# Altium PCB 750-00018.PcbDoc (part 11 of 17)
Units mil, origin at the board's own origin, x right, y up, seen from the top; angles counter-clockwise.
Board outline 7086.64 x 6299.21 mil, 8 copper layers (Top Layer, L2, L3, L4, L5, L6, L7, Bottom Layer), stack 60.6 mil thick; 1356 components, 1054 nets, 4851 pads, 4296 vias.
Unrouted connection lines stored in the file: 12.
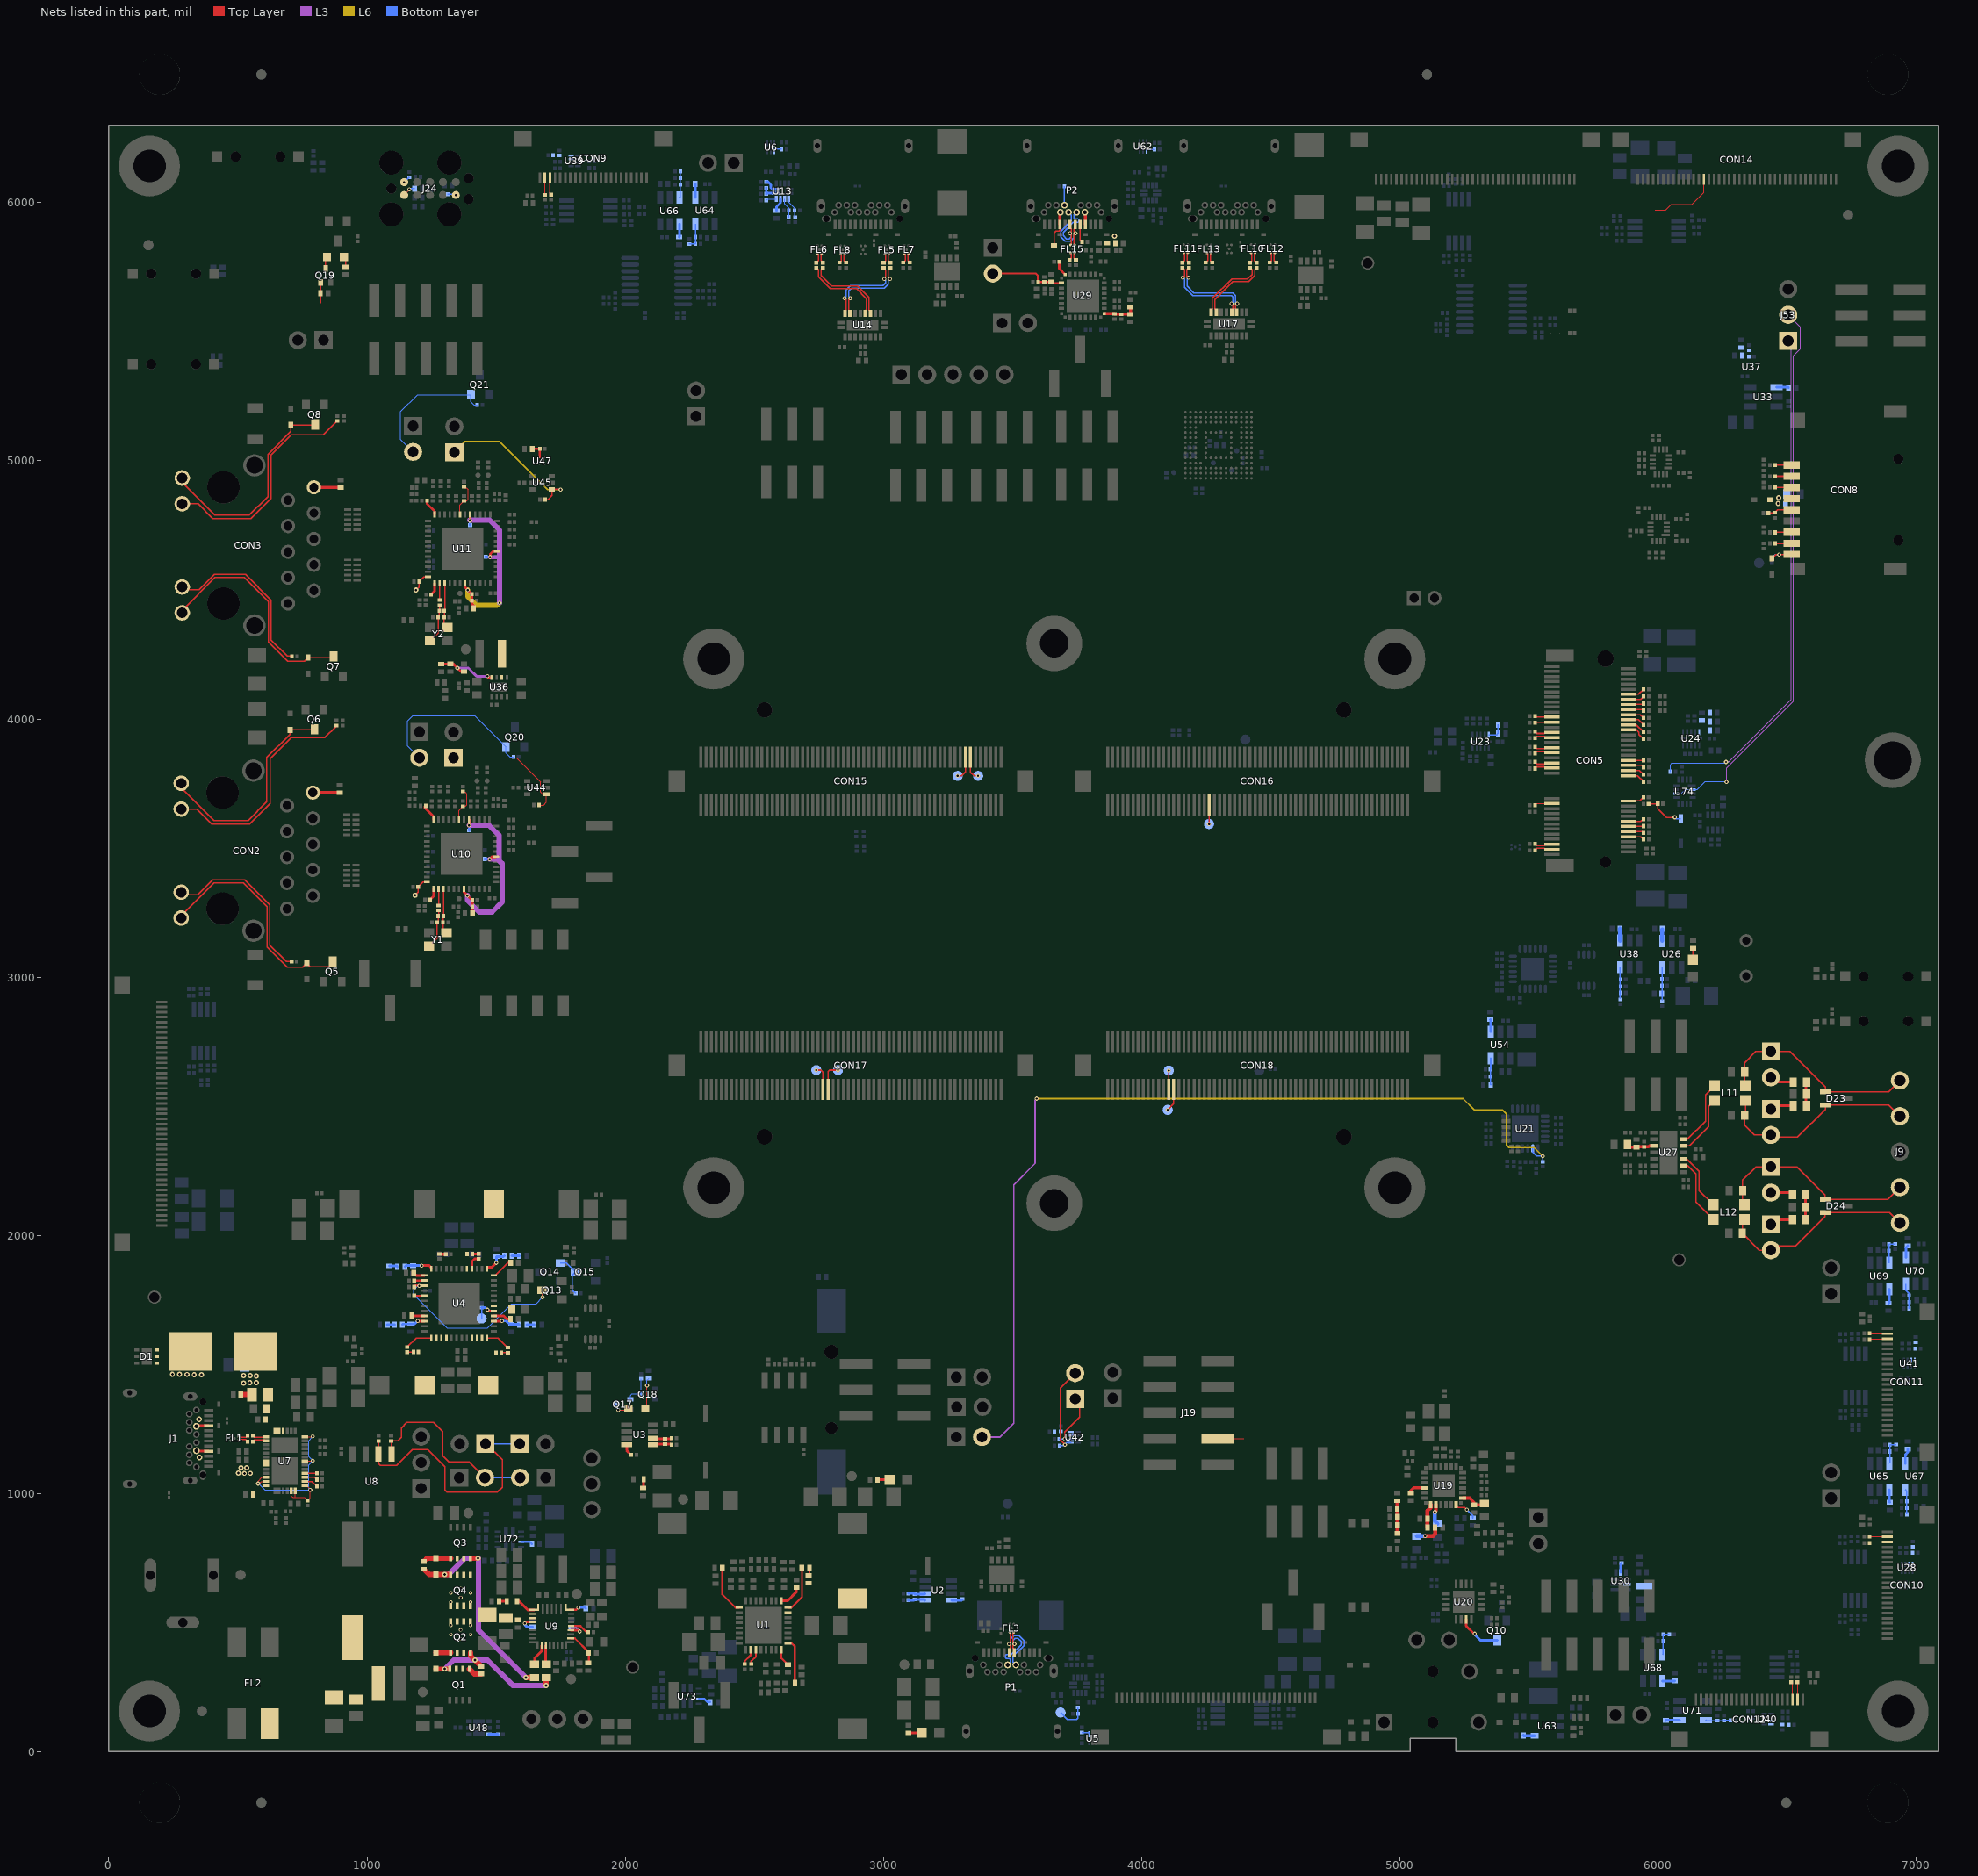
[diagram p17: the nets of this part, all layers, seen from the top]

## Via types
v1: diameter 16, hole 8, Top Layer to Bottom Layer, tented both sides, 3994 vias
v2: diameter 20, hole 10, Top Layer to Bottom Layer, tented both sides, 266 vias
v3: diameter 14, hole 7.87, Top Layer to Bottom Layer, tented both sides, 24 vias
v4: diameter 22, hole 12, Top Layer to Bottom Layer, tented both sides, 8 vias
v5: diameter 24, hole 12, Top Layer to Bottom Layer, tented both sides, 4 vias

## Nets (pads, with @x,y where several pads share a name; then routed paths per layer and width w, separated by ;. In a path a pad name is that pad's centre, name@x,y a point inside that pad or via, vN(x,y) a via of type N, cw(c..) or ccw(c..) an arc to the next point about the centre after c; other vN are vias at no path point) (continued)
NetC20_1: C20.1 R12.2 | length 32
  Top Layer w8: C20.1@2709.93,682.36 2713.4,685.83 R12.2@2713.4,712.9
NetC20_2: C20.2 L3.1 U1.15
NetC21_2: C21.2 U1.8 | length 67.9
  Top Layer w8: U1.8@2604.21,395.25 2604.21,362.79 C21.2@2629.25,337.75
NetC25_2: C25.2 U1.17 | length 90.1
  Top Layer w10: U1.17@2604.21,584.25 2627.99,584.25 2663.13,619.39 C25.2@2663.13,635.98
NetC28_1: C28.1 R25.2 U2.2 | length 66.9
  Bottom Layer w10: R25.2@3096.59,613.02 3118.41,613.02 C28.1@3121.49,609.94 3158.47,609.94 U2.2@3161.1,612.57
NetC28_2: C28.2 R19.2 U2.1 | length 67.4
  Bottom Layer w10: R19.2@3096.41,586.99 3118.23,586.99 C28.2@3121.49,590.25 3157.83,590.25 U2.1@3161.1,586.98
NetC29_1: C29.1 R29.2 U3.2 | length 72.2
  Top Layer w10: U3.2@2107.75,1214.56 2109.94,1212.37 C29.1@2153.58,1212.37 ; C29.1@2154.12,1211.84 2177.32,1211.84 R29.2@2178.94,1213.46
NetC29_2: C29.2 R24.2 U3.1 | length 73
  Top Layer w10: U3.1@2107.75,1188.97 2110.32,1191.54 C29.2@2153.5,1191.54 ; C29.2@2154.52,1191.75 2174.59,1191.75 R24.2@2178.94,1187.4
NetC32_1: C32.1 R27.2 | length 25.1
  Top Layer w5: R27.2@1154.82,1547.92 1178.59,1547.92 C32.1@1179.51,1548.85
NetC32_2: C32.2 L4.1 U4.2 U4.3 U4.4
NetC33_1: C33.1 U4.45 | length 46.9
  Top Layer w10: C33.1@1175.9,1687.67 U4.45@1222.82,1687.67
NetC37_1: C37.1 U4.16 | length 70.3
  Top Layer w10: U4.16@1490.54,1687.67 1529.48,1687.67 1541.45,1675.7 C37.1@1555.87,1675.7
NetC38_1: C38.1 U4.24 | length 86
  Top Layer w5: U4.24@1490.54,1845.15 1497.07,1845.15 1546.41,1894.5 C38.1@1556.1,1894.5
NetC42_1: C42.1 R31.2 | length 25.7
  Top Layer w5: C42.1@1519.85,1546.47 1520.41,1545.91 R31.2@1545.32,1545.91
NetC42_2: C42.2 L5.1 U4.9 U4.10 U4.11
NetC49_1: C49.1 R37.2 | length 24.6
  Top Layer w10: C49.1@1407.55,1927.83 1431.01,1927.83 R37.2@1431.8,1928.63
NetC49_2: C49.2 L6.1 U4.29
NetC56_2: C56.2 R39.1 | length 28.7
  Bottom Layer w10: C56.2@1078.52,1653.96 1078.72,1654.16 R39.1@1107.19,1654.16
NetC57_1: C57.1 U4.18 | length 2.9
  Top Layer w10: C57.1@1558.32,1712.31 C57.1@1560.36,1714.36
NetC59_1: C59.1 R39.2 U4.46 | length 92
  Top Layer w10: v1@1195.86,1668.64 1196.51,1667.99 U4.46@1222.82,1667.99
  Bottom Layer w10: R39.2@1136.71,1654.16 1139.08,1656.52 C59.1@1167.67,1656.52 1183.74,1656.52 v1(1195.58,1668.36)
NetC60_1: C60.1 R41.2 U4.25 | length 104.3
  Top Layer w10: U4.25@1464.95,1870.74 1464.95,1876.36 1483.32,1876.36 v1(1500.6,1893.64)
  Bottom Layer w10: v1(1500.6,1893.64) 1501.15,1894.19 C60.1@1501.15,1917.24 1528.66,1917.24 R41.2@1531.86,1920.44
NetC61_2: C61.2 R41.1 | length 28.5
  Bottom Layer w10: R41.1@1561.39,1920.44 1589.02,1920.44 C61.2@1589.65,1921.06
NetC62_1: C62.1 R42.2 U4.15 | length 105.3
  Top Layer w10: U4.15@1490.54,1667.99 1521.84,1667.99 v1(1522.38,1668.52)
  Bottom Layer w10: v1(1522.38,1668.52) 1539.36,1668.52 1552.54,1655.34 C62.1@1558.25,1655.34 1587.42,1655.34 R42.2@1589.36,1653.4
NetC64_2: C64.2 R42.1 | length 28.6
  Bottom Layer w10: R42.1@1618.89,1653.4 1647.26,1653.4 C64.2@1647.41,1653.55
NetC66_1: C66.1 R43.2 | length 24.9
  Top Layer w12: R43.2@1280.96,1927.5 C66.1@1304.92,1927.5 ; R43.2@1281.68,1927.72 R43.2@1282.32,1927.08
NetC75_2: C75.2 U7.38
NetC76_2: C76.2 C77.2 C78.2 C79.2 F1.2 U7.23 U7.24 U7.25 U7.32 U7.33
  other v2: 524.66,1078.48 548.13,1078.61 501.8,1079.92 511.38,1100 534.17,1099.82 521.66,1428.44 546.44,1429.21 571.82,1430.2 571.82,1454.65 521.42,1456.22 546.87,1456.67
NetC77_1: C77.1 R54.2 | length 37.3
  Top Layer w20: R54.2@515.75,1383.62 C77.1@553.07,1383.62
NetC88_1: C88.1 D4.2 Q1.1 Q1.2 Q1.3 Q2.1 Q2.2 Q2.3 | length 111.3
  Top Layer w20: D4.2@1266.35,384.42 1267.21,383.57 Q2.1@1323.78,383.57 ; Q1.1@1396.11,320.5 1415.3,301.31 C88.1@1441.74,301.31
NetC88_2: C88.2 D4.1 Q1.4 Q2.4 R65.1 | length 592.5
  Top Layer w20: D4.1@1266.35,321.43 1267.28,320.5 v2(1300.46,320.5) Q1.4@1314.74,320.5 ; Q2.4@1400.55,383.57 1400.55,372.2 v2(1417.4,355.36) 1417.4,355.18 C88.2@1438.7,333.87 ; v2(1693.36,257.02) 1693.8,257.46 R65.1@1693.8,287
  L3 w20: v2(1300.46,320.5) 1335.32,355.36 v2(1417.4,355.36) 1466.35,355.36 1564.68,257.02 v2(1693.36,257.02)
NetC89_1: C89.1 C94.1 C95.1 Q2.5 Q2.6 Q2.7 Q2.8 Q4.5 Q4.6 Q4.7 Q4.8 U9.2 U9.3
  other v3: 1362.17,436.44 1323.78,454.24 1400.55,454.24 1362.17,472.07 1323.78,489.87 1400.55,489.87 1324.05,579.42 1400.82,579.42 1362.43,597.22 1324.05,615.05 1400.82,615.05 1362.43,632.85
NetC92_1: C92.1 D5.2 Q3.1 Q3.2 Q3.3 Q4.1 Q4.2 Q4.3 | length 106.2
  Top Layer w20: C92.1@1222.45,739.48 1233.08,750.11 D5.2@1266.35,750.11 1267.67,748.79 Q3.1@1323.74,748.79
NetC92_2: C92.2 D5.1 Q3.4 Q4.4 R66.1 | length 852.9
  Top Layer w20: C92.2@1223.13,704.06 1240.07,687.12 D5.1@1266.35,687.12 v2(1300.42,687.12) Q4.4@1318.94,687.12 ; Q3.4@1406.18,748.79 1429.46,748.79 v2(1429.63,748.96) ; v2(1615.67,287.2) 1615.77,287.09 R66.1@1648.69,287.09
  L3 w20: v2@1301.05,687.28 1317.16,687.28 1345.93,716.05 1379.72,749.85 v2@1429.63,749.85 ; v2@1431.42,749.85 1431.42,471.45 v2(1615.67,287.2)
NetC96_1: C96.1 U9.4 | length 69.7
  Top Layer w10: v1(1611.12,496.74) 1616.68,502.31 U9.4@1640.77,502.31
  Bottom Layer w10: v1(1611.12,496.74) 1611.12,492.16 1619.67,483.6 C96.1@1640.77,483.6
NetC97_1: C97.1 U9.19 | length 76.1
  Top Layer w10: U9.19@1789.39,470.81 1818.78,470.81 1823.01,466.58 v1(1823.01,465.51)
  Bottom Layer w10: C97.1@1791.09,482.7 1806.89,482.7 1823.01,466.58 v1(1823.01,465.51)
NetC109_1: C109.1 U9.24 | length 68.4
  Top Layer w8: U9.24@1783.49,549.55 1809.39,549.55 v1(1818.16,558.33)
  Bottom Layer w8: v1(1818.16,558.33) 1844.24,558.33 C109.1@1847.1,555.47
NetC110_1: C110.1 C111.1 C115.1 FL2.4 L9.1
NetC119_2: C119.2 C120.1 C121.1 C122.1 FB1.2 U10.19 U10.30 U10.41 | length 813.8
  Top Layer w10: U10.19@1375.38,3342.81 1375.38,3329.15 v1@1388.45,3316.08 ; v1(1388.57,3316.2) 1406.85,3297.92 C120.1@1407.59,3297.92 1407.76,3297.76 C119.2@1407.76,3272.58 ; v1(1395.07,3588.07) U10.41@1395.07,3610.53 ; FB1.2@1408.34,3246.58 C119.2@1408.34,3268.25 ; v1(1474.49,3457.27) 1484.05,3466.83 U10.30@1499.4,3466.83
  L3 w20: v1(1388.57,3316.2) 1388.57,3297.68 1434.04,3252.21 1484.17,3252.21 1522.64,3290.68 1522.64,3440.37 1505.94,3457.07 ; v1(1395.07,3588.07) 1472.44,3588.07 1510.78,3549.74 1510.78,3461.9 1505.94,3457.07 ; v1@1474.7,3457.07 1505.94,3457.07
  Bottom Layer w10: v1(1395.07,3588.07) 1395.32,3587.82 C122.1@1395.32,3568.31 ; C121.1@1456.09,3457.7 1474.06,3457.7 v1(1474.49,3457.27)
NetC138_2: C138.2 CON2.1 | length 103.9
  Top Layer w12: CON2.1@790,3715 892.87,3715 C138.2@893.57,3714.3
NetC139_1: C139.1 R87.1 U10.43 | length 136
  Top Layer w4: U10.43@1355.7,3610.53 1355.7,3646.43 C139.1@1371.42,3662.15 1381.08,3662.15 1386.8,3667.87 1386.8,3709.27 1379.43,3716.64 R87.1@1371.13,3716.64
NetC142_1: C142.1 R91.2 R92.1 Y1.1 | length 152.6
  Top Layer w5: Y1.1@1240.44,3120.98 1270.94,3151.48 C142.1@1270.94,3212.5 1275.65,3217.22 R92.1@1275.65,3236.84 1276.99,3238.17 R91.2@1276.99,3258.45
NetC143_2: C143.2 R92.2 U10.15 Y1.3 | length 177
  Top Layer w5: U10.15@1296.64,3342.81 1296.64,3238.14 R92.2@1295.34,3236.84 1295.34,3213.44 C143.2@1294.28,3212.39 1294.28,3185.25 Y1.3@1307.37,3172.17
NetC145_2: C145.2 C146.1 C147.1 C148.1 FB3.2 U11.19 U11.30 U11.41 | length 829.9
  Top Layer w10: U11.19@1379.32,4525.13 1379.32,4509.99 v1(1389.71,4499.6) 1405.39,4483.93 C148.1@1405.9,4483.93 1405.9,4458.21 C146.1@1405.69,4458 1405.69,4446.45 1412.28,4439.86 FB3.2@1412.28,4428.89 ; v1(1398.86,4768.87) 1399.01,4769.01 U11.41@1399.01,4792.84 ; v1(1476.78,4627.17) 1477.21,4627.6 1477.21,4639.06 1487.3,4649.14 U11.30@1503.34,4649.14
  L3 w15: v1(1476.78,4627.17) 1512.75,4627.17 1513.29,4627.71
  L3 w20: v1@1397.59,4770.06 1474.96,4770.06 1513.29,4731.72 1513.29,4627.71 v1(1513.29,4450.2)
  L6 w20: v1(1389.71,4499.6) 1389.71,4474.29 1423.68,4440.32 1503.41,4440.32 v1(1513.29,4450.2)
  Bottom Layer w10: v1(1398.86,4768.87) 1399.27,4768.46 C145.2@1399.27,4750.64 ; C147.1@1459.44,4627.97 1459.6,4628.13 1475.82,4628.13 v1(1476.78,4627.17)
NetC164_2: C164.2 CON3.1 | length 103.9
  Top Layer w12: CON3.1@793.94,4897.31 896.81,4897.31 C164.2@897.51,4896.61
NetC165_1: C165.1 R120.1 U11.43 | length 132.9
  Top Layer w4: U11.43@1359.64,4792.84 1359.64,4828.74 C165.1@1375.36,4844.47 1385.03,4844.47 1390.74,4850.18 1390.74,4889.07 1384.72,4895.09 R120.1@1375.07,4895.09
NetC168_1: C168.1 R124.2 R125.1 Y2.1 | length 152.6
  Top Layer w5: Y2.1@1244.38,4303.3 1275.25,4334.16 C168.1@1275.25,4394.48 1279.6,4398.83 R125.1@1279.6,4419.16 1280.93,4420.49 R124.2@1280.93,4440.76
NetC169_2: C169.2 R125.2 U11.15 Y2.3 | length 177
  Top Layer w5: U11.15@1300.58,4525.13 1300.58,4420.46 R125.2@1299.28,4419.16 1299.28,4395.76 C169.2@1298.23,4394.7 1298.23,4367.57 Y2.3@1311.31,4354.48
NetC194_1: C194.1 U19.24 | length 92
  Top Layer w6: U19.24@5217.9,956.94 5217.9,954.28 5225.96,946.22 5250.92,946.22 v1(5259.28,937.86)
  Bottom Layer w6: v1(5259.28,937.86) 5281.67,915.48 C194.1@5281.67,905.94
NetC195_2: C195.2 C196.1 U19.1 | length 102.8
  Top Layer w12: U19.1@5243.49,982.53 5270.88,982.53 5286.87,966.53 C196.1@5286.87,956.12 5323.46,956.12 C195.2@5327.53,960.19
NetC202_1: C202.1 U19.20 | length 78.7
  Top Layer w15: v1(5135.53,928.2) 5139.16,931.82 U19.20@5139.16,956.94
  Bottom Layer w15: v1(5135.53,928.2) 5135.53,892.76 C202.1@5144.76,883.54
NetC203_1: C203.1 R274.1 R276.1 | length 98.8
  Top Layer w15: v1(5097.49,835.46) 5127.96,835.46 5136.3,843.8 R276.1@5136.3,867.94
  Bottom Layer w15: C203.1@5065.31,834.86 5096.89,834.86 v1(5097.49,835.46)
NetC209_1: C209.1 C212.2 FB8.1 R204.1 R205.1 | length 127.9
  Top Layer w15: C212.2@4990.14,972.69 4990.14,942.66 R205.1@4989.7,942.22 4990.61,941.31 C209.1@4990.61,909.31 R204.1@4990.61,876.54 ; R204.1@4990.44,876.37 R204.1@4990.61,876.54 ; FB8.1@4990.5,845.69 4990.61,845.8 R204.1@4990.61,876.54
NetC222_1: C222.1 C254.1 FB9.1 U27.3 | length 108
  Top Layer w12: FB9.1@5881.17,2351.44 5890.62,2341.99 C254.1@5916.39,2341.99 5917.35,2342.95 C222.1@5946.16,2342.95 5962.55,2342.95 5966.16,2346.56 U27.3@5983.31,2346.56
NetC231_1: C231.1 R224.1 U23.11 | length 72.3
  Bottom Layer w5: U23.11@5344.43,3938.54 5374.3,3938.54 C231.1@5380.32,3944.56 5380.32,3978.18 R224.1@5380.55,3978.41
NetC233_1: C233.1 R222.1 R223.1 R225.1 U24.11
NetC246_1: C246.1 U26.4 | length 47.5
  Bottom Layer w10: C246.1@6015.61,3184.48 C246.1@6018.11,3186.98
  Bottom Layer w15: U26.4@6015.61,3140.5 C246.1@6015.61,3184.48
NetC247_1: C247.1 R26.1 R244.2 R248.2 U26.3 | length 126.8
  Bottom Layer w6: R26.1@6015.61,2911.34 6015.61,2966.47 U26.3@6015.61,3038.14
NetC248_1: C248.1 CON5.37 | length 70.5
  Top Layer w6: C248.1@5523,3833.36 5530.24,3826.13 5559.52,3826.13 5563.24,3829.84 CON5.37@5588.98,3829.84
NetC249_1: C249.1 CON5.35 | length 71.2
  Top Layer w6: C249.1@5522.92,3807.69 5530.36,3815.13 5559.17,3815.13 5564.14,3810.16 CON5.35@5588.98,3810.16
NetC256_2: C256.2 R285.1 U28.7 U28.8
NetC257_2: C257.2 R353.1 U39.7 U39.8
NetC258_2: C258.2 R377.1 U40.7 U40.8
NetC259_2: C259.2 R378.1 U41.7 U41.8
NetC260_2: C260.2 R519.1 U42.7 U42.8
NetC262_1: C262.1 R526.2 R530.2 R538.2 U37.5
NetC264_1: C264.1 R275.1 R277.2 | length 91.3
  Top Layer w10: R277.2@6572.49,2494.15 R275.1@6572.49,2585.41
NetC265_1: C265.1 D23.1 J7.1 J9.5 L11.3 | length 803.6
  Top Layer w5: L11.3@6338.8,2579.56 6334.96,2583.4 C265.1@6334.96,2633.34 6334.96,2668.51 6378.33,2711.88 J7.1@6436.53,2711.88 6509.91,2711.88 6647.18,2574.61 D23.1@6647.18,2555.88 6892.49,2555.88 J9.5@6936.31,2599.7
NetC266_1: C266.1 D23.2 J8.2 J9.4 L11.2 | length 797.6
  Top Layer w5: C266.1@6332.97,2466.38 6338.8,2472.22 L11.2@6338.8,2522.47 ; C266.1@6334.96,2466.38 6334.96,2426.28 6372.38,2388.86 J8.2@6436.53,2388.86 6444.57,2380.81 6539.88,2380.81 6647.18,2488.11 D23.2@6647.18,2504.7 6893.51,2504.7 J9.4@6936.31,2461.9
NetC269_1: C269.1 R537.2 U47.5 | length 61.3
  Top Layer w9: R537.2@1639.63,5045.69 1640.14,5046.21 C269.1@1668.96,5046.21 1668.85,5046.09 U47.5@1668.85,5014.54
NetC270_2: C270.2 U48.3 | length 35
  Bottom Layer w12: U48.3@1471.37,66.79 1505.66,66.79 C270.2@1506.14,67.28
NetC273_1: C273.1 D25.1 FB13.2 P2.A4 P2.A9 P2.B4 P2.B9 | length 194
  Top Layer w5: D25.1@3660.93,5833.49 3660.93,5882.14 3668.15,5889.35 3679,5889.35 3683.3,5893.65 P2.A9@3683.3,5914.96
  Top Layer w12: P2.A9@3683.3,5914.96 3683.3,5960.64 P2.B4@3685.26,5962.6 ; P2.B9@3779.75,5962.6 3781.72,5960.63 P2.A4@3781.72,5914.96
  other v2: 3895.4,5869.81
NetC276_1: C276.1 U19.16 | length 64.7
  Top Layer w12: C276.1@5041.72,1002.44 5041.72,1010.03 5053.58,1021.9 U19.16@5093.89,1021.9
NetC277_1: C277.1 R282.1 R284.2 | length 91.3
  Top Layer w10: R284.2@6570.26,2052.23 R282.1@6570.26,2143.49
NetC278_1: C278.1 D24.1 J9.2 J10.1 L12.3 | length 809.9
  Top Layer w5: L12.3@6333.91,2118.96 6327.25,2125.61 C278.1@6327.25,2173.61 6327.25,2214.15 6378.95,2265.84 J10.1@6436.53,2265.84 6538.06,2265.84 6647.15,2156.75 D24.1@6647.15,2139.72 6889.72,2139.72 J9.2@6936.31,2186.31
NetC279_1: C279.1 D24.2 J9.1 J11.2 L12.2 | length 780
  Top Layer w5: L12.2@6333.91,2061.87 6326.16,2054.11 C279.1@6326.16,2008.1 6391.44,1942.82 J11.2@6436.53,1942.82 6452.28,1958.58 6532.39,1958.58 6647.15,2073.34 D24.2@6647.15,2088.54 6896.29,2088.54 J9.1@6936.31,2048.52
NetC280_2: C280.2 U29.16 | length 58
  Top Layer w10: C280.2@3681.1,5770.85 3681.1,5743.9 U29.16@3703.08,5721.92
NetC281_1: C281.1 J12.2 R288.2 R291.1 U29.18 | length 295.9
  Top Layer w8: J12.2@3423.44,5724.98 3424.18,5725.72 3589.81,5725.72 3598.35,5717.18 R288.2@3598.35,5692.93 3598.88,5692.39 R291.1@3622.71,5692.39 3650.43,5692.39 C281.1@3650.56,5692.53 3654.63,5688.45 U29.18@3689.3,5688.45
NetC285_2: C285.2 C287.1 C289.1 FB14.1 U29.1 | length 129.1
  Top Layer w12: U29.1@3854.65,5570.34 3858.59,5570.34 3893.26,5570.34 C285.2@3894.9,5568.7 ; C285.2@3895.49,5568.12 C287.1@3920.59,5568.12 ; C287.1@3920.92,5567.79 C289.1@3956.46,5567.79 ; FB14.1@3956.27,5595.28 3956.57,5594.99 C289.1@3956.57,5567.9
NetC293_1: C293.1 R451.2 U4.36 | length 111.3
  Top Layer w10: v1(1211.36,1882.98) 1241.19,1882.98 1248.41,1875.76 U4.36@1248.41,1870.74
  Bottom Layer w10: R451.2@1146.85,1878.86 1150.88,1882.89 C293.1@1178.17,1882.89 1178.26,1882.98 v1(1211.36,1882.98)
NetC296_1: C296.1 CON8.5 R311.2 | length 95.1
  Top Layer w6: R311.2@6427.08,4797.49 6450.58,4797.49 C296.1@6451.59,4798.5 6463.31,4810.22 CON8.5@6516.95,4810.22
NetC297_1: C297.1 CON8.4 D28.1 R318.2
  other v2: 6464.41,4834.93 6466.93,4856.69
NetC299_1: C299.1 U33.4 | length 47
  Bottom Layer w10: U33.4@6458.49,5284.6 6504.41,5284.6 C299.1@6505.21,5283.79
NetC306_2: C306.2 R231.2 R301.1 U36.4 | length 248.9
  Top Layer w10: C306.2@1287.05,4212.5 1287.74,4213.19 R231.2@1322.8,4213.19 1333.69,4213.19 v1(1349.6,4197.27) 1363.22,4183.66 R301.1@1375.56,4183.66 ; v1(1466.25,4165.61) 1471.04,4160.81 U36.4@1482.38,4160.81
  L3 w10: v1(1349.6,4197.27) 1392.39,4197.27 1424.05,4165.61 v1(1466.25,4165.61)
NetC312_1: C312.1 U14.19 | length 320.1
  Top Layer w5: v1(2849.46,5629.92) 2855.46,5623.92 2855.46,5584.96 U14.19@2850.76,5580.26 ; C312.1@3000.55,5747.58 3008.97,5739.16 3008.97,5710.44 v1(3002.95,5704.41)
  Bottom Layer w5: v1(2849.46,5629.92) 2855.58,5636.04 2855.58,5662.23 2872.44,5679.09 2998.88,5679.09 3008.41,5688.61 v1@3008.41,5698.96 ; v1(3002.95,5704.41) v1@3008.41,5698.96 ; v1@3008.41,5699.14 v1@3008.41,5698.96
NetC312_2: C312.2 FL5.C1 | length 38.8
  Top Layer w5: C312.2@3000.55,5767.27 3008.17,5774.88 3008.17,5798.78 FL5.C1@3005.26,5801.69
NetC313_1: C313.1 U14.18 | length 320.5
  Top Layer w5: U14.18@2870.44,5579.51 2865.46,5584.49 2865.46,5624.11 v1(2871.28,5629.92) ; v1(3024.77,5704.41) 3023.68,5704.41 3018.97,5709.12 3018.97,5740.42 C313.1@3026.14,5747.58
  Bottom Layer w5: v1(2871.28,5629.92) 2865.58,5635.62 2865.58,5658.09 2876.58,5669.09 3003.03,5669.09 3018.41,5684.47 3018.41,5699.14 v1@3023.68,5704.41
NetC313_2: C313.2 FL5.C2 | length 38.9
  Top Layer w5: FL5.C2@3021.01,5801.69 3018.17,5798.84 3018.17,5775.24 C313.2@3026.14,5767.27
NetC314_1: C314.1 U14.15 | length 318.5
  Top Layer w5: C314.1@2739.73,5747.58 2748.01,5739.29 2748.01,5713.1 2794.34,5666.77 2896.06,5666.77 2934.2,5628.63 2934.2,5584.96 2929.5,5580.26 U14.15@2929.5,5571.14
NetC314_2: C314.2 FL6.C1 | length 39.2
  Top Layer w5: C314.2@2739.73,5767.27 2747.79,5775.33 2747.79,5798.47 FL6.C1@2744.49,5801.77
NetC315_1: C315.1 U14.14 | length 318.3
  Top Layer w5: C315.1@2765.5,5747.58 2758.01,5740.1 2758.01,5717.24 2798.49,5676.77 2900.21,5676.77 2944.2,5632.77 2944.2,5584.49 2949.19,5579.51 U14.14@2949.18,5571.14
NetC315_2: C315.2 FL6.C2 | length 38.7
  Top Layer w5: FL6.C2@2760.24,5801.77 2757.79,5799.32 2757.79,5774.98 C315.2@2765.5,5767.27
NetC316_1: C316.1 U17.19 | length 276.6
  Top Layer w5: U17.19@4269.24,5575.26 4269.24,5584.06 4273.86,5588.68 4273.86,5628.81 4349.31,5704.26 4409.88,5704.26 4427.32,5721.7 4427.32,5739.66 C316.1@4419.4,5747.58
NetC316_2: C316.2 FL10.C1 | length 42.7
  Top Layer w5: C316.2@4419.4,5767.27 4426.64,5774.51 4426.64,5802.9 FL10.C1@4423.74,5805.8
NetC317_1: C317.1 U17.18 | length 276.6
  Top Layer w5: U17.18@4288.92,5575.26 4288.92,5583.28 4283.86,5588.34 4283.86,5624.67 4353.45,5694.26 4414.02,5694.26 4437.32,5717.56 4437.32,5740.02 C317.1@4444.88,5747.58
NetC317_2: C317.2 FL10.C2 | length 43.1
  Top Layer w5: FL10.C2@4439.49,5805.8 4436.64,5802.96 4436.64,5775.51 C317.2@4444.88,5767.27
NetC318_1: C318.1 U17.15 | length 353.2
  Top Layer w5: C318.1@4157.5,5747.58 4165.31,5739.77 4165.31,5713.89 4160.61,5709.18 v1(4159.52,5709.18) ; v1(4347.61,5608.66) 4352.96,5603.31 4352.96,5588.61 4347.98,5583.63 U17.15@4347.98,5575.26
  Bottom Layer w5: v1@4160.61,5709.18 4165.88,5703.91 4165.88,5672.44 4198,5640.32 4348.09,5640.32 4353.58,5634.83 4353.58,5614.63 v1(4347.61,5608.66)
NetC318_2: C318.2 FL11.C1 | length 42.6
  Top Layer w5: C318.2@4157.5,5767.27 4165.87,5775.63 4165.87,5802.34 FL11.C1@4162.97,5805.24
NetC319_1: C319.1 U17.14 | length 353.1
  Top Layer w5: v1(4181.34,5709.18) 4175.31,5715.21 4175.31,5739.72 C319.1@4183.17,5747.58 ; U17.14@4367.66,5575.26 4367.66,5584.37 4362.96,5589.08 4362.96,5602.19 v1(4369.43,5608.66)
  Bottom Layer w5: v1(4181.34,5709.18) 4175.88,5703.73 4175.88,5676.59 4202.14,5650.32 4352.24,5650.32 4363.58,5638.98 4363.58,5614.51 v1(4369.43,5608.66)
NetC319_2: C319.2 FL11.C2 | length 42.2
  Top Layer w5: FL11.C2@4178.71,5805.24 4175.87,5802.39 4175.87,5774.57 C319.2@4183.17,5767.27
NetC326_1: C326.1 U30.8 | length 37.4
  Bottom Layer w10: U30.8@5855.43,694.58 5855.43,727.7 C326.1@5858.45,730.72
NetC329_1: C329.1 U64.4 | length 53.3
  Bottom Layer w10: C329.1@2270.58,6073.02 2271.3,6072.29 U64.4@2271.3,6020.04
NetC330_1: C330.1 U65.4 | length 49.3
  Bottom Layer w10: U65.4@6894.65,1014.7 6894.65,968.61 C330.1@6896.94,966.33
NetC331_1: C331.1 R577.2 R578.2 U64.3 | length 102
  Bottom Layer w5: R577.2@2247.45,5839.87 2270.93,5839.87 C331.1@2271.95,5840.89 R578.2@2271.94,5866.84 2271.3,5867.48 U64.3@2271.3,5917.67
NetC332_1: C332.1 R579.2 R580.2 U65.3 | length 97.5
  Bottom Layer w5: U65.3@6894.65,1117.06 6897.26,1119.66 R580.2@6897.26,1162.95 6897.26,1188.56 C332.1@6897.45,1188.75 6920.94,1188.75 R579.2@6921.76,1189.57
NetC335_1: C335.1 U66.4 | length 50.7
  Bottom Layer w10: C335.1@2208.75,5866.64 2209.87,5867.76 U66.4@2209.87,5916.91
NetC340_1: C340.1 U67.4 | length 58.8
  Bottom Layer w10: U67.4@6957.34,1117.23 6957.34,1150.35 6966.18,1159.19 C340.1@6966.18,1172.32
NetC341_1: C341.1 R583.2 R584.2 U66.3 | length 103.6
  Bottom Layer w5: U66.3@2209.87,6019.27 2213.08,6022.49 R584.2@2213.08,6069.44 C341.1@2213.07,6094.96 2213.07,6121.37 R583.2@2213.21,6121.5
NetC342_1: C342.1 R585.2 R586.2 U67.3 | length 97.6
  Bottom Layer w5: U67.3@6957.34,1014.87 6963.16,1009.05 R586.2@6963.16,970.82 6963.16,945.28 C342.1@6963.31,945.14 6963.31,919.98 R585.2@6963.16,919.84
NetC345_1: C345.1 U68.4 | length 47.2
  Bottom Layer w10: U68.4@6017.12,273.97 6063.55,273.97 C345.1@6064.12,274.54
NetC346_1: C346.1 U69.4 | length 54.2
  Bottom Layer w10: C346.1@6892.76,1737.67 6894.65,1739.56 U69.4@6894.65,1791.13
NetC347_1: C347.1 R589.2 R591.2 U68.3 | length 102.9
  Bottom Layer w5: U68.3@6017.12,376.33 6019.39,378.6 R591.2@6019.39,428.56 C347.1@6019.38,454.24 R589.2@6043.4,454.24
NetC348_1: C348.1 R590.2 R592.2 U69.3 | length 97.5
  Bottom Layer w5: U69.3@6894.65,1893.49 6894.65,1940.52 R592.2@6894.3,1940.87 6894.3,1966.15 C348.1@6894.35,1966.19 6917.82,1966.19 R590.2@6918.63,1967.01
NetC351_1: C351.1 U70.4 | length 47.9
  Bottom Layer w10: U70.4@6959.78,1914.13 6959.78,1952.79 C351.1@6966.33,1959.34
NetC352_1: C352.1 U71.4 | length 52.5
  Bottom Layer w10: C352.1@6030.54,121.22 6032.22,122.9 U71.4@6082.38,122.9
NetC362_1: C362.1 R595.2 R597.2 U70.3 | length 99.8
  Bottom Layer w5: U70.3@6959.78,1811.77 6959.78,1787.21 6971.38,1775.61 R597.2@6971.38,1767.24 6971.23,1767.09 C362.1@6971.23,1742.09 6971.38,1741.95 R595.2@6971.38,1716.89
NetC363_1: C363.1 R596.2 R598.2 U71.3 | length 96.6
  Bottom Layer w5: U71.3@6184.74,122.9 6187.52,120.12 R598.2@6229.63,120.12 C363.1@6255.48,120.12 6256.38,121.02 R596.2@6279.86,121.02
NetC369_2: C369.2 U63.4 | length 43.3
  Bottom Layer w12: C369.2@5478.93,63.24 5480.24,61.93 U63.4@5521.65,61.93
NetC370_1: C370.1 U38.4 | length 47.2
  Bottom Layer w15: C370.1@5851.65,3187.8 5852.42,3187.03 U38.4@5852.42,3140.94
NetC371_1: C371.1 R425.2 R426.2 R443.2 U38.3 | length 120.9
  Bottom Layer w6: R443.2@5852.42,2917.68 5852.42,2964.47 U38.3@5852.42,3038.57
NetC372_1: C372.1 U54.4 | length 47.5
  Bottom Layer w10: C372.1@5350.43,2835.96 5351.3,2835.09 U54.4@5351.3,2788.8
NetC373_1: C373.1 R432.2 R434.2 U54.3 | length 103.1
  Bottom Layer w6: U54.3@5351.3,2686.43 5351.3,2642.69 R434.2@5350.78,2642.16 5350.78,2615.42 C373.1@5350.63,2615.28 5350.63,2585.51 R432.2@5352,2584.14
NetC388_2: C388.2 R451.1 | length 32.6
  Bottom Layer w10: C388.2@1085.88,1881.56 1114.63,1881.56 R451.1@1117.33,1878.86
NetC389_1: C389.1 U4.37 | length 46.4
  Top Layer w10: C389.1@1180.38,1854.7 1189.93,1845.15 U4.37@1222.82,1845.15
NetC417_1: C417.1 U72.11 | length 45.7
  Bottom Layer w8: U72.11@1596.35,813.56 1630.22,813.56 C417.1@1638.59,805.19
NetC418_1: C418.1 U73.11 | length 49.2
  Bottom Layer w8: U73.11@2285.4,205.6 2305.64,205.6 2318.83,192.4 C418.1@2329.16,192.4
NetCON2_11: CON2.11 D9.1 Q6.3 | length 838
  Top Layer w5: CON2.11@279.37,3750.83 279.37,3734.28 406.56,3607.09 539.36,3607.09 611.63,3679.36 611.63,3850.94 700.66,3939.97 D9.1@700.66,3956.6 ; D9.1@702.41,3958.36 Q6.3@794.83,3958.36
NetCON2_12: CON2.12 R81.2 | length 883.9
  Top Layer w5: CON2.12@279.37,3650.83 341.46,3650.83 398.51,3593.77 545.45,3593.77 624.3,3672.63 624.3,3846.68 705.67,3928.06 836.2,3928.06 R81.2@880.75,3972.61
NetCON2_13: CON2.13 R85.2 | length 679.6
  Top Layer w5: CON2.13@279.37,3329.17 290.1,3318.44 343.9,3318.44 402.85,3377.39 525.98,3377.39 623.68,3279.69 623.68,3124.29 686.94,3061.03 R85.2@708.05,3061.03
NetCON2_14: CON2.14 D8.1 Q5.3 | length 900.7
  Top Layer w4: D8.1@767.09,3052.71 D8.1@767.09,3055.48
  Top Layer w5: CON2.14@279.37,3229.17 279.37,3237.58 407.12,3365.34 521.01,3365.34 613.62,3272.72 613.62,3116.98 691.29,3039.32 750.94,3039.32 D8.1@766.54,3054.93 ; D8.1@767.09,3052.71 780.12,3039.69 852.24,3039.69 867,3054.45 Q5.3@867,3059.7
NetCON3_11: CON3.11 D13.1 Q8.3 | length 840.4
  Top Layer w5: CON3.11@283.31,4933.14 283.31,4916.59 410.5,4789.4 543.3,4789.4 615.58,4861.68 615.58,5024.71 704.6,5113.73 D13.1@704.6,5138.92 797.02,5138.92 Q8.3@798.77,5140.67
NetCON3_12: CON3.12 R114.2 | length 880.6
  Top Layer w5: CON3.12@283.31,4833.14 345.4,4833.14 402.46,4776.09 549.39,4776.09 628.24,4854.94 628.24,5023.46 705.94,5101.16 830.93,5101.16 R114.2@884.69,5154.92
NetCON3_13: CON3.13 R118.2 | length 676.2
  Top Layer w5: CON3.13@283.31,4511.49 294.04,4500.75 349.24,4500.75 408.18,4559.7 528.98,4559.7 628.28,4460.4 628.28,4305.94 690.88,4243.34 R118.2@709.1,4243.34
NetCON3_14: CON3.14 D12.1 Q7.3 | length 884.3
  Top Layer w5: CON3.14@283.31,4411.49 283.31,4419.9 411.06,4547.65 524.95,4547.65 617.57,4455.03 617.57,4299.3 693.04,4223.82 757.07,4223.82 D12.1@771.03,4237.79 870.95,4237.79 Q7.3@870.95,4242.02
NetCON5_3: CON5.3 R270.1 | length 71.8
  Top Layer w5: R270.1@5522.92,3491.09 5531.87,3500.04 5558.57,3500.04 5563.41,3495.2 CON5.3@5588.98,3495.2
NetCON5_5: CON5.5 R269.1 | length 70.9
  Top Layer w5: R269.1@5522.92,3516.77 5529.66,3510.04 5558.92,3510.04 5563.76,3514.88 CON5.5@5588.98,3514.88
NetCON5_8: CON5.8 R268.2 | length 61.9
  Top Layer w5: CON5.8@5886.23,3544.41 5932.26,3544.41 R268.2@5943.45,3533.22
NetCON5_10: CON5.10 R267.2 | length 59
  Top Layer w5: CON5.10@5886.23,3564.1 5939.13,3564.1 R267.2@5943.45,3559.77
NetCON5_12: CON5.12 R266.2 | length 58.3
  Top Layer w5: CON5.12@5886.23,3583.78 5940.92,3583.78 R266.2@5943.45,3586.32
NetCON5_14: CON5.14 R265.2 | length 61.6
  Top Layer w5: CON5.14@5886.23,3603.47 5932.93,3603.47 R265.2@5943.45,3613.99
NetCON5_21: CON5.21 R263.1 | length 68.5
  Top Layer w4: R263.1@5522.92,3666.42 5528.87,3672.36 CON5.21@5588.98,3672.36
NetCON5_22: CON5.22 R261.2 | length 63.1
  Top Layer w5: CON5.22@5886.23,3682.21 5928.63,3682.21 R261.2@5943.26,3696.84
NetCON5_32: CON5.32 R258.2 | length 66.6
  Top Layer w5: CON5.32@5886.23,3779.69 5920.88,3779.69 R258.2@5943.45,3757.11
NetCON5_34: CON5.34 R257.2 | length 63.7
  Top Layer w5: CON5.34@5886.23,3800.32 5927.76,3800.32 R257.2@5943.45,3784.63
NetCON5_36: CON5.36 R256.2 | length 60.5
  Top Layer w5: CON5.36@5886.23,3820 5935.59,3820 R256.2@5943.45,3812.14
NetCON5_38: CON5.38 R254.2 | length 57.2
  Top Layer w5: CON5.38@5886.23,3839.69 R254.2@5943.42,3839.69
NetCON5_41: CON5.41 R283.1 | length 71.2
  Top Layer w6: R283.1@5522.92,3866.74 5530.36,3874.18 5559.17,3874.18 5564.14,3869.21 CON5.41@5588.98,3869.21
NetCON5_43: CON5.43 R281.1 | length 70.5
  Top Layer w6: R281.1@5523,3892.41 5530.24,3885.18 5559.52,3885.18 5563.24,3888.9 CON5.43@5588.98,3888.9
NetCON5_47: CON5.47 R251.1 | length 71.2
  Top Layer w6: R251.1@5522.92,3925.8 5530.36,3933.24 5559.17,3933.24 5564.14,3928.27 CON5.47@5588.98,3928.27
NetCON5_49: CON5.49 R250.1 | length 70.5
  Top Layer w6: R250.1@5523,3951.47 5530.24,3944.24 5559.52,3944.24 5563.24,3947.95 CON5.49@5588.98,3947.95
NetCON5_50: CON5.50 R249.2 | length 77.6
  Top Layer w5: CON5.50@5886.23,3957.8 5917.4,3957.8 5926.35,3948.84 5926.35,3939.29 R249.2@5943.45,3922.19
NetCON5_52: CON5.52 R247.2 | length 68.7
  Top Layer w5: CON5.52@5886.23,3977.48 5915.68,3977.48 R247.2@5943.45,3949.71
NetCON5_53: CON5.53 R246.1 | length 67
  Top Layer w5: R246.1@5522.92,3985.14 5525.11,3987.32 CON5.53@5588.98,3987.32
NetCON5_54: CON5.54 R245.2 | length 65.5
  Top Layer w5: CON5.54@5886.23,3997.17 5923.51,3997.17 R245.2@5943.45,3977.22
NetCON5_55: CON5.55 R243.1 | length 67.6
  Top Layer w5: R243.1@5522.92,4010.79 5526.7,4007.01 CON5.55@5588.98,4007.01
NetCON5_56: CON5.56 R242.2 | length 62.2
  Top Layer w5: CON5.56@5886.23,4016.85 5931.33,4016.85 R242.2@5943.45,4004.73
NetCON5_58: CON5.58 R241.2 | length 59
  Top Layer w5: CON5.58@5886.23,4036.54 5939.16,4036.54 R241.2@5943.45,4032.25
NetCON5_60: CON5.60 R240.2 | length 58.7
  Top Layer w5: CON5.60@5886.23,4056.22 5939.91,4056.22 R240.2@5943.45,4059.76
NetCON5_62: CON5.62 R238.2 | length 61.9
  Top Layer w5: CON5.62@5886.23,4075.91 5932.09,4075.91 R238.2@5943.45,4087.27
NetCON5_64: CON5.64 R236.2 | length 65.2
  Top Layer w5: CON5.64@5886.23,4095.59 5924.26,4095.59 R236.2@5943.45,4114.79
NetCON8_1: CON8.1 R316.2 | length 64.3
  Top Layer w6: R316.2@6452.64,4983.49 6516.9,4983.49 CON8.1@6516.95,4983.44
NetCON8_2: CON8.2 R317.2 | length 64.6
  Top Layer w6: R317.2@6452.46,4939.89 6452.7,4940.14 CON8.2@6516.95,4940.14
NetCON8_3: CON8.3 R309.2 | length 63.8
  Top Layer w6: R309.2@6453.1,4896.83 CON8.3@6516.95,4896.83
NetCON8_7: CON8.7 R313.2 | length 64.8
  Top Layer w6: R313.2@6452.46,4722.86 6453.2,4723.6 CON8.7@6516.95,4723.6
NetCON8_8: CON8.8 R315.2 | length 64.6
  Top Layer w6: R315.2@6452.46,4679.99 6452.76,4680.3 CON8.8@6516.95,4680.3
NetCON8_9: CON8.9 D27.1 R304.2 | length 115.4
  Top Layer w5: D27.1@6440.88,4622.01 6455.86,4636.99 v1(6468.67,4636.99) CON8.9@6516.95,4636.99
  Bottom Layer w5: R304.2@6440.88,4623.98 6453.89,4636.99 v1(6468.67,4636.99)
NetCON9_20: CON9.20 R367.2 | length 66.3
  Top Layer w4: CON9.20@1708.37,6095.14 1708.37,6035.23 R367.2@1712.84,6030.75
NetCON9_21: CON9.21 R368.2 | length 64.7
  Top Layer w4: R368.2@1688.35,6030.55 1688.68,6030.88 CON9.21@1688.68,6095.14
NetCON10_20: CON10.20 R369.2 | length 71.2
  Top Layer w4: R369.2@6818.22,808.66 6822.18,812.61 CON10.20@6887.83,812.61
NetCON10_21: CON10.21 R370.2 | length 70.1
  Top Layer w4: R370.2@6818.22,833.59 6886.53,833.59 CON10.21@6887.83,832.3
NetCON11_20: CON11.20 R379.2 | length 70.6
  Top Layer w4: R379.2@6818.68,1596 6822.27,1599.59 CON11.20@6887.83,1599.59
NetCON11_21: CON11.21 R380.2 | length 69.9
  Top Layer w4: R380.2@6818.51,1620.58 6819.82,1619.27 CON11.21@6887.83,1619.27
NetCON12_20: CON12.20 R381.2 | length 69.6
  Top Layer w4: R381.2@6515.2,269.38 6520.62,263.95 CON12.20@6520.62,202.02
NetCON12_21: CON12.21 R382.2 | length 67.9
  Top Layer w4: R382.2@6539.01,269.41 6540.3,268.12 CON12.21@6540.3,202.02
NetCON14_27: CON14.27 SB2.1 | length 268.4
  Top Layer w4: 5988.04,5971.26 6029.08,5971.26 6050.59,5992.78 6130.38,5992.78 6177.07,6039.47 CON14.27@6177.07,6090.59
NetCON15_105: CON15.105 TP20.1 | length 92.9
  Top Layer w5: v1(3287.29,3779.59) 3301.53,3779.59 3316.93,3794.99 CON15.105@3316.93,3851.92
NetCON15_107: CON15.107 TP36.1 | length 93.3
  Top Layer w5: CON15.107@3336.62,3851.92 3336.62,3794.23 3351.25,3779.59 v1(3366.17,3779.59)
NetCON16_42: CON16.42 TP38.1 | length 74.1
  Top Layer w5: v1(4260.66,3593.3) 4261.81,3594.46 CON16.42@4261.81,3666.88
NetCON17_69: CON17.69 TP23.1 | length 109.7
  Top Layer w6: CON17.69@2785.44,2565.4 2785.44,2634.7 2790.83,2640.09 v1(2823.65,2640.09)
NetCON17_71: CON17.71 TP35.1 | length 95.9
  Top Layer w6: v1(2739.96,2640.09) 2757.89,2640.09 2765.75,2632.23 CON17.71@2765.75,2565.4
NetCON18_93: CON18.93 TP37.1 | length 88.9
  Top Layer w5: v1(4100.65,2486.2) 4124.02,2509.57 CON18.93@4124.02,2565.4
NetCON18_95: CON18.95 TP34.1 | length 73.1
  Top Layer w5: CON18.95@4104.33,2565.4 4104.33,2637.95 v1(4104.75,2638.37)
NetD1_4: D1.4 D1.5 D1.6 F1.1 J1.A4 J1.A9 J1.B4 J1.B9 | length 96.9
  Top Layer w10: J1.B4@338.92,1166.13 340.88,1164.17 J1.A9@386.55,1164.17 ; J1.B9@338.92,1260.62 340.89,1262.59 J1.A4@386.55,1262.59
  other v2: 330.52,1460.53 359.27,1460.4 273.79,1461.43 302.55,1461.3 245.83,1462.21
  other v4: 350.8,1139.9 350.17,1287.29
NetD22_1: D22.1 R259.2 R264.1 | length 160.3
  Top Layer w5: R264.1@5962.95,3670.74 R259.2@5998.6,3670.74 ; R259.2@5998.6,3672 5998.6,3652.73 6032.07,3619.27 v1(6064.36,3619.27)
  Bottom Layer w5: v1(6064.36,3619.27) 6070.54,3613.08 D22.1@6087.55,3613.08
NetFL1_C1: FL1.C1 R53.1 | length 39.8
  Top Layer w5: FL1.C1@502.64,1205.96 505.51,1208.83 529.42,1208.83 R53.1@537.79,1200.46
NetFL1_C2: FL1.C2 R52.1 | length 39
  Top Layer w5: FL1.C2@502.64,1221.71 505.51,1218.83 531.28,1218.83 R52.1@537.79,1225.34
NetFL3_A1: FL3.A1 P1.A7 P1.B7 | length 289
  Top Layer w5: FL3.A1@3504.49,462.77 3501.64,459.93 3501.64,423.18 v1(3507.29,417.53) 3501.64,411.88 3501.64,401.58 3506.52,396.7 P1.A7@3506.52,384.25
  Bottom Layer w5: P1.B7@3480.93,336.61 3491.5,347.18 3491.5,358.04 3488.31,361.24 3475.6,361.24 3472.89,363.95 3472.89,373.53 3475.6,376.24 3494.73,376.24 3533.15,414.66 3533.15,426.98 3520.71,439.42 3509.63,439.42 3501.29,431.09 3501.29,423.54 v1(3507.29,417.53)
NetFL3_A2: FL3.A2 P1.A6 P1.B6 | length 288.5
  Top Layer w5: P1.A6@3486.84,384.25 3486.84,397.15 3491.64,401.95 3491.64,411.37 v1(3485.48,417.53) 3491.64,423.69 3491.64,459.87 FL3.A2@3488.74,462.77
  Bottom Layer w5: v1(3485.48,417.53) 3491.29,423.34 3491.29,435.23 3505.48,449.42 3524.85,449.42 3543.15,431.12 3543.15,410.51 3501.5,368.87 3501.5,347.54 P1.B6@3512.43,336.61
NetFL7_C1: FL7.C1 R336.2 | length 38.8
  Top Layer w5: R336.2@3076.28,5767.41 3084.11,5775.24 3084.11,5798.87 FL7.C1@3081.21,5801.77
NetFL7_C2: FL7.C2 R337.2 | length 38.7
  Top Layer w5: FL7.C2@3096.95,5801.77 3094.11,5798.92 3094.11,5775.14 R337.2@3101.84,5767.41
NetFL8_C1: FL8.C1 R339.1 | length 37.6
  Top Layer w5: R339.1@2829.95,5767.41 2837.09,5774.54 2837.09,5797.92 FL8.C1@2834.18,5800.83
NetFL8_C2: FL8.C2 R340.1 | length 37.9
  Top Layer w5: FL8.C2@2849.93,5800.83 2847.09,5797.98 2847.09,5775.43 R340.1@2855.1,5767.41
NetFL12_C1: FL12.C1 R341.2 | length 42.9
  Top Layer w5: R341.2@4495.34,5767.41 4502.91,5774.98 4502.91,5802.66 FL12.C1@4499.68,5805.88
NetFL12_C2: FL12.C2 R342.2 | length 42.8
  Top Layer w5: FL12.C2@4515.43,5805.88 4512.91,5803.36 4512.91,5775.39 R342.2@4520.89,5767.41
NetFL13_C1: FL13.C1 R344.1 | length 42.6
  Top Layer w5: R344.1@4247.2,5766.97 4255.56,5775.33 4255.56,5802.04 FL13.C1@4252.66,5804.94
NetFL13_C2: FL13.C2 R345.1 | length 42.2
  Top Layer w5: FL13.C2@4268.41,5804.94 4265.56,5802.1 4265.56,5774.28 R345.1@4272.87,5766.97
NetFL15_A1: FL15.A1 P2.A7 P2.B7 | length 289
  Top Layer w5: P2.A7@3722.67,5914.96 3722.67,5902.51 3727.55,5897.63 3727.55,5887.33 v1(3721.9,5881.68) 3727.55,5876.03 3727.55,5839.28 FL15.A1@3724.7,5836.44
  Bottom Layer w5: v1(3721.9,5881.68) 3727.9,5875.68 3727.9,5868.12 3719.56,5859.79 3708.49,5859.79 3696.04,5872.23 3696.04,5884.55 3734.46,5922.97 3753.59,5922.97 3756.3,5925.68 3756.3,5935.26 3753.59,5937.97 3740.88,5937.97 3737.69,5941.17 3737.69,5952.03 P2.B7@3748.26,5962.6
NetFL15_A2: FL15.A2 P2.A6 P2.B6 | length 292.7
  Top Layer w5: FL15.A2@3740.45,5836.44 3737.55,5839.34 3737.55,5875.52 v1(3743.71,5881.68) 3737.55,5887.84 3737.55,5897.26 3742.35,5902.06 P2.A6@3742.35,5919.08
  Bottom Layer w5: P2.B6@3716.76,5962.6 3727.69,5951.67 3727.69,5930.34 3686.04,5888.7 3686.04,5868.09 3704.34,5849.79 3723.71,5849.79 3737.9,5863.98 3737.9,5875.87 v1(3743.71,5881.68)
NetFL15_C1: FL15.C1 R325.1 | length 31.4
  Top Layer w5: R325.1@3720.05,5777.84 3727.61,5785.39 3727.61,5802.04 FL15.C1@3724.7,5804.94
NetFL15_C2: FL15.C2 R401.1 | length 31.4
  Top Layer w5: FL15.C2@3740.45,5804.94 3737.61,5802.1 3737.61,5785.51 R401.1@3745.23,5777.88
NetJ7_2: J7.2 R275.2 | length 93.7
  Top Layer w10: J7.2@6436.53,2611.88 6454.64,2593.76 R275.2@6522.73,2593.76
NetJ8_1: J8.1 R277.1 | length 91.9
  Top Layer w10: J8.1@6436.53,2488.86 6450.17,2502.5 R277.1@6522.73,2502.5
NetJ10_2: J10.2 R282.2 | length 87.1
  Top Layer w10: J10.2@6436.53,2165.84 6512.89,2165.84 R282.2@6520.49,2158.23
NetJ11_1: J11.1 R284.1 | length 91.3
  Top Layer w10: J11.1@6436.53,2042.82 6454.28,2060.58 R284.1@6520.49,2060.58
NetJ19_8: J19.8 SB1.1 | length 100.1
  Top Layer w4: J19.8@4294.8,1212.78 4394.57,1212.78 4394.8,1213.01
NetJ24_1: J24.1 R321.1 | length 51.2
  Top Layer w4: J24.1@1143.79,6029.38 1163.85,6049.44 v1(1163.85,6050.71)
  Bottom Layer w5: v1(1163.85,6050.71) 1167.1,6053.95 R321.1@1184.03,6053.95
NetJ24_5: J24.5 R510.2 | length 32.6
  Bottom Layer w5: R510.2@1312.24,6032.01 1341.16,6032.01 v1(1343.79,6029.38)
NetJ24_10: J24.10 R517.1 | length 28
  Bottom Layer w5: v1(1143.79,6079.38) 1162.97,6098.56 R517.1@1163.83,6098.56
NetJ30_1: J30.1 R520.2 U42.6 | length 232.6
  Top Layer w5: v1(3701.38,1211.73) 3701.38,1238.57 3759.18,1296.37 3759.18,1349.86 J30.1@3742.35,1366.69
  Bottom Layer w5: R520.2@3681.44,1210.09 3682.08,1210.74 3700.39,1210.74 v1(3701.38,1211.73) 3702.36,1210.74 U42.6@3727.1,1210.74
NetJ30_2: J30.2 R521.2 U42.5 | length 360.6
  Top Layer w5: v1(3702.95,1188.68) 3684.39,1207.24 3684.39,1409.21 3692.84,1417.65 3741.87,1466.69 J30.2@3742.35,1466.69
  Bottom Layer w5: R521.2@3681.91,1185.32 3699.59,1185.32 v1(3702.95,1188.68) 3702.95,1189.72 3710.2,1196.96 U42.5@3727.1,1196.96
NetJ31_1: J31.1 R331.1 U44.1 | length 505.5
  Top Layer w4: J31.1@1334.56,3849.05 1578.72,3849.05 1671.66,3756.11 1671.66,3716.34 1679.15,3708.85 U44.1@1694.67,3708.85 1694.67,3677.98 1683.41,3666.72 R331.1@1666.17,3666.72
NetJ32_2: J32.2 Q20.2 R570.1 | length 659.9
  Bottom Layer w4: J32.2@1202.44,3849.86 1156.77,3895.53 1156.77,3991.62 1177.93,4012.78 1416.6,4012.78 Q20.2@1538,3891.39 1538,3868.31 1553.75,3852.55 R570.1@1567.37,3852.55
NetJ34_1: J34.1 R427.1 U45.1 | length 597
  Top Layer w5: R427.1@1689.93,4849.93 1700.43,4849.93 1716.13,4865.63 U45.1@1716.13,4889.52 1742.24,4889.52 1742.67,4889.95 1747.64,4889.95 v1(1749.22,4888.37)
  L6 w5: J34.1@1337.86,5033.26 1380.2,5075.6 1511.59,5075.6 1698.82,4888.37 v1(1749.22,4888.37)
NetJ35_2: J35.2 Q21.2 R571.1 | length 532.2
  Bottom Layer w4: J35.2@1178.25,5034.63 1130.45,5082.44 1130.45,5190.5 1196.37,5256.42 Q21.2@1402.03,5256.42 1402.03,5227.8 1412.88,5216.94 R571.1@1426.59,5216.94
NetJ36_2: J36.2 R303.1 U21.14 | length 3643
  L3 w6: J36.2@3381.53,1219.04 3451.94,1219.04 3504.82,1271.91 3504.82,2196.08 3587.19,2278.46 3587.19,2523.49 v1(3593.23,2529.53)
  L6 w6: v1(3593.23,2529.53) 5244.8,2529.5 5287.95,2486.35 5396.33,2486.35 5411.9,2470.78 5411.9,2349.75 5421.75,2339.9 5520.09,2339.9 v1(5553.05,2306.94)
  Bottom Layer w5: U21.14@5514.79,2336.4 5514.79,2322.35 5530.21,2306.94 v1(5553.05,2306.94) 5553.28,2306.71 R303.1@5553.28,2285.03
NetJ37_1: J37.1 J40.1 R64.2 U8.6 | length 1055.4
  Top Layer w5: R64.2@1044.35,1203.93 1044.22,1203.8 U8.6@1044.22,1153.44 1044.22,1115.62 1051.32,1108.51 1113.61,1108.51 1175.11,1170.01 1234.95,1170.01 1301.64,1103.32 1301.64,1013.32 1309.8,1005.15 1504.35,1005.15 1523.67,1024.47 1523.67,1130.76 1461.76,1192.67 J40.1@1458.44,1192.67
  Bottom Layer w5: J40.1@1458.44,1192.67 J37.1@1591.42,1192.67
NetJ41_2: J41.2 J42.2 R63.2 U8.5 | length 744.5
  Top Layer w5: U8.5@1094.22,1153.44 1094.22,1203.33 R63.2@1093.31,1204.24 1119.68,1204.24 1133.02,1217.57 1133.02,1254.09 1154.25,1275.32 1257.78,1275.32 1293.73,1239.37 1293.73,1146.38 1317.34,1122.78 1395.45,1122.78 J41.2@1456.69,1061.54
  Bottom Layer w5: J41.2@1456.69,1061.54 J42.2@1592.8,1061.54
NetJ53_1: J53.1 R606.1 | length 1993.6
  L3 w4: v1(6263.07,3833.66) 6273.47,3833.66 6514.72,4074.91 6514.72,5454.29 J53.1@6503.82,5465.2
  Bottom Layer w4: R606.1@6047.09,3796.05 6047.09,3822.8 6053.53,3829.24 6258.65,3829.24 v1(6263.07,3833.66)
NetJ53_2: J53.2 U74.2 U74.10 | length 2160.5
  L3 w4: v1(6264.87,3756.29) 6264.87,3810.43 6523.21,4068.76 6523.21,5406.42 6551.5,5434.71 6551.5,5517.52 J53.2@6503.82,5565.2
  Bottom Layer w4: U74.10@6071.23,3711.09 6089.45,3711.09 6105.2,3726.84 U74.2@6134.22,3726.84 6151.85,3726.84 6182.25,3757.24 6263.92,3757.24 v1(6264.87,3756.29)
NetL11_1: L11.1 U27.12 | length 239.9
  Top Layer w5: U27.12@6097.48,2346.56 6121.07,2346.56 6196.24,2421.72 6196.24,2499.98 L11.1@6218.72,2522.47
NetL11_4: L11.4 U27.13 | length 266.7
  Top Layer w5: U27.13@6097.48,2372.15 6113.01,2372.15 6183.67,2442.81 6183.67,2544.5 L11.4@6218.72,2579.56
NetL12_1: L12.1 U27.9 | length 265.8
  Top Layer w5: U27.9@6097.48,2269.79 6113.97,2269.79 6146.54,2237.21 6146.54,2129.16 L12.1@6213.83,2061.87
NetL12_4: L12.4 U27.10 | length 232.7
  Top Layer w5: U27.10@6097.48,2295.37 6111.35,2295.37 6158.61,2248.12 6158.61,2174.18 L12.4@6213.83,2118.96
NetL13_1: L13.1 U36.2
NetL14_1: L14.1 U30.2
NetLED1_1: LED1.1 R2.2 | length 34.4
  Top Layer w10: R2.2@2068.96,1021.39 2070.96,1023.39 LED1.1@2070.96,1054.97
NetLED2_2: LED2.2 R10.2 | length 51.7
  Top Layer w10: R10.2@3096.71,73.14 3147.49,73.14 LED2.2@3148.13,73.77
NetLED3_2: LED3.2 R13.2 | length 47.3
  Top Layer w10: R13.2@2977.05,1053.37 LED3.2@3024.3,1053.37
NetLED4_1: LED4.1 R75.2 | length 29.8
  Top Layer w10: R75.2@1511.81,582.36 LED4.1@1541.64,582.36
NetLED4_2: LED4.2 U9.1 | length 80.2
  Top Layer w10: LED4.2@1581.01,582.36 1589.24,582.36 1622.06,549.55 U9.1@1647.66,549.55
NetLED5_2: LED5.2 R239.1 | length 44.2
  Top Layer w6: LED5.2@6134.31,3067.99 6135.05,3068.73 R239.1@6135.05,3111.87
NetLED8_1: LED8.1 Q17.3 | length 67.6
  Top Layer w4: v1(1972.92,1322.99) 2005.95,1322.99 LED8.1@2012.4,1329.43
  Bottom Layer w4: Q17.3@1964.7,1345.04 1964.7,1331.2 v1(1972.92,1322.99)
NetLED8_2: LED8.2 R531.1 | length 123.9
  Top Layer w4: LED8.2@2077.36,1329.43 2085.2,1337.27 2084.09,1338.38 v1(2084.09,1418.89)
  Bottom Layer w4: v1(2084.09,1418.89) 2084.09,1439.15 R531.1@2091.5,1446.56
NetLED10_1: LED10.1 Q19.3 | length 38.3
  Top Layer w5: Q19.3@839.59,5745.46 LED10.1@839.59,5783.79
NetLED10_2: LED10.2 R408.1 | length 32.1
  Top Layer w5: R408.1@916.86,5750.76 LED10.2@916.86,5782.88
NetP2_A5: P2.A5 R569.2 | length 70
  Top Layer w5: P2.A5@3762.04,5914.96 3762.04,5854.99 R569.2@3769.15,5847.88
NetP2_B5: P2.B5 R568.2 | length 72.9
  Bottom Layer w5: P2.B5@3701.01,5990.16 R568.2@3701.01,6063.05
NetQ10_3: Q10.3 U20.15 | length 170
  Top Layer w10: U20.15@5256.85,512.44 5256.85,487.25 5287.07,457.03 v1(5289.45,457.03)
  Bottom Layer w10: v1(5289.45,457.03) 5289.45,454.65 5312.92,431.18 Q10.3@5377,431.18
NetQ13_3: Q13.3 R36.2 U4.39 | length 719
  Top Layer w4: Q13.3@1678.66,1787.69 1678.66,1761.26 v1(1679.6,1760.32)
  Top Layer w8: R36.2@1182.3,1800.37 1187.71,1805.78 U4.39@1222.82,1805.78
  Bottom Layer w4: v1(1201.93,1804.61) 1195.92,1804.61 1180.85,1789.54 1180.85,1770.21 1310.19,1640.87 1466.57,1640.87 1560.65,1734.95 1654.24,1734.95 v1(1679.6,1760.32)
NetQ14_1: Q14.1 Q15.3 R149.1 | length 168
  Bottom Layer w5: Q14.1@1747.91,1893.21 1772.97,1893.21 Q15.3@1807.74,1858.44 1795.13,1845.82 1795.13,1788.09 R149.1@1808.02,1775.2
NetQ17_1: Q17.1 Q18.3 R417.1 | length 118.9
  Bottom Layer w4: Q17.1@2019.82,1364.72 2019.82,1380.14 2025.21,1385.54 2061.1,1385.54 Q18.3@2061.47,1385.16 2061.47,1444.16 R417.1@2061.15,1444.48
NetQ19_1: Q19.1 R410.2 SB4.2 | length 79.1
  Top Layer w5: 819.91,5611.26 Q19.1@819.91,5690.35
NetR1_1: R1.1 U1.25 | length 188.4
  Top Layer w8: R1.1@2376.04,712.1 2376.04,609.39 2426.73,558.7 U1.25@2440.76,558.7
NetR5_1: R5.1 U1.9 | length 172.9
  Top Layer w8: U1.9@2629.76,420.8 2643.79,420.8 2656.79,407.8 R5.1@2656.79,267.31
NetR12_1: R12.1 U1.16 | length 185.2
  Top Layer w8: U1.16@2629.76,558.7 2643.79,558.7 2684.32,599.23 2684.32,712.45 R12.1@2683.87,712.9
NetR16_2: R16.2 U1.2 | length 65.3
  Top Layer w8: R16.2@2462.44,339.76 2462.44,350.8 2486.01,374.37 U1.2@2486.01,395.25
NetR17_2: R17.2 U1.3 | length 62.9
  Top Layer w8: R17.2@2488.19,339.57 2488.19,350.68 2505.71,368.2 U1.3@2505.71,395.25
NetR20_1: R20.1 U2.8 | length 42.1
  Bottom Layer w10: U2.8@3263.47,586.98 3303.22,586.98 R20.1@3304.9,588.65
NetR21_1: R21.1 U3.8 | length 46.9
  Top Layer w10: U3.8@2005.39,1188.97 2005.39,1167.17 R21.1@2023.13,1149.42
NetR27_1: R27.1 U4.1 | length 108.3
  Top Layer w5: R27.1@1154.82,1567.61 1190.24,1603.03 U4.1@1248.41,1603.03
NetR31_1: R31.1 U4.12 | length 95.9
  Top Layer w5: U4.12@1464.95,1603.03 1507.89,1603.03 R31.1@1545.32,1565.6
NetR32_2: R32.2 U4.41 | length 40.5
  Top Layer w8: R32.2@1182.46,1766.18 1182.69,1766.41 U4.41@1222.82,1766.41
NetR34_2: R34.2 U4.38 | length 40.7
  Top Layer w8: R34.2@1182.3,1825.12 1182.65,1825.47 U4.38@1222.82,1825.47
NetR37_1: R37.1 U4.28 | length 58
  Top Layer w10: U4.28@1405.89,1870.74 1405.89,1898.43 1416.4,1908.94 R37.1@1431.8,1908.94
NetR47_1: R47.1 R567.1 TP26.1 | length 122.7
  Bottom Layer w5: TP26.1@3685.77,151.91 3712.92,124.76 3747.73,124.76 3753.52,130.56 R47.1@3753.52,147.38 3752.9,148 R567.1@3752.9,171.6
NetR49_2: R49.2 U5.1 | length 34
  Bottom Layer w5: R49.2@3768.25,73.85 3796.28,73.85 U5.1@3796.28,67.94
NetR51_2: R51.2 U7.5 U7.6 U7.7 U7.13 U7.19 U7.36 U7.37 | length 775.9
  Top Layer w4: U7.37@607.06,1047.13 591.63,1047.13 583.22,1038.72 v1(578.08,1038.72) 578.08,1047.75 593.21,1062.88 U7.36@607.06,1062.88 ; U7.5@706.48,1010.71 706.48,990.44 712.56,984.36 722.18,984.36 757.83,984.36 R51.2@769.42,972.76 780.02,983.36 v1(780.02,1014.13) 780.02,1017.3 765.95,1031.37 U7.7@758.64,1031.37 ; 722.22,984.39 U7.6@722.22,1010.71 ; U7.13@758.64,1125.87 788.87,1125.87 v1(790.11,1127.1) ; U7.19@758.64,1220.36 788.87,1220.36 v1(790.11,1221.59)
  Bottom Layer w4: v1(578.08,1038.72) 579.31,1038.72 604.11,1013.92 779.82,1013.92 v1(780.02,1014.13) 774.5,1019.65 774.5,1111.5 v1(790.11,1127.1) 773.69,1143.52 773.69,1205.18 v1(790.11,1221.59)
NetR52_2: R52.2 U7.26 | length 54.6
  Top Layer w5: R52.2@557.48,1225.34 557.48,1224.42 564.4,1217.5 604.19,1217.5 U7.26@607.06,1220.37
NetR53_2: R53.2 U7.27 | length 53.8
  Top Layer w5: R53.2@557.48,1200.46 557.48,1200.57 564.4,1207.5 604.19,1207.5 U7.27@607.06,1204.62
NetR55_1: R55.1 U7.9 | length 51.5
  Top Layer w5: U7.9@758.64,1062.87 797.35,1062.87 R55.1@806.42,1053.79
NetR56_1: R56.1 U7.8 | length 55.8
  Top Layer w5: U7.8@758.64,1047.12 786.98,1047.12 R56.1@806.42,1027.67
NetR57_1: R57.1 U7.10 | length 47.9
  Top Layer w5: U7.10@758.64,1078.62 806.08,1078.62 R57.1@806.42,1078.96
NetR65_2: R65.2 U9.11 | length 73.5
  Top Layer w10: U9.11@1691.95,411.75 1691.95,340.84 R65.2@1693.8,339
NetR66_2: R66.2 U9.10 | length 84.1
  Top Layer w10: R66.2@1648.69,339.09 1648.69,362.92 1676.2,390.44 U9.10@1676.2,411.75
NetR70_1: R70.1 R72.1 U9.17 | length 134.6
  Top Layer w8: U9.17@1788.41,439.31 1804.76,439.31 1858.54,385.54 1858.54,345.79 R70.1@1856.79,344.04
NetR74_1: R74.1 U9.20 | length 75.9
  Top Layer w8: U9.20@1790.38,486.56 1826.64,486.56 1849.82,463.38 R74.1@1856.64,463.38
NetR76_2: R76.2 U10.13 | length 47.8
  Top Layer w10: R76.2@1244.53,3300.28 1257.27,3313.02 U10.13@1257.27,3342.81
NetR77_2: R77.2 U10.48 | length 65.4
  Top Layer w10: R77.2@1224.8,3662.46 1224.8,3655.13 1257.27,3622.65 U10.48@1257.27,3610.53
NetR90_1: R90.1 TP13.1 U10.12 | length 79.2
  Top Layer w5: v1(1185.58,3317.34) 1197.73,3329.49 R90.1@1197.73,3349.91 1216.22,3368.4 U10.12@1231.68,3368.4
NetR91_1: R91.1 U10.14 | length 64.7
  Top Layer w5: R91.1@1276.96,3278.16 U10.14@1276.96,3342.81
NetR109_2: R109.2 U11.13 | length 47.8
  Top Layer w10: R109.2@1248.47,4482.59 1261.21,4495.34 U11.13@1261.21,4525.13
NetR110_2: R110.2 U11.48 | length 66.8
  Top Layer w10: R110.2@1232.64,4847.78 1232.64,4833.54 1261.21,4804.97 U11.48@1261.21,4792.84
NetR123_1: R123.1 TP17.1 U11.12 | length 79.2
  Top Layer w5: v1(1189.52,4499.65) 1201.67,4511.8 R123.1@1201.67,4532.22 1220.16,4550.72 U11.12@1235.62,4550.72
NetR124_1: R124.1 U11.14 | length 64.7
  Top Layer w5: R124.1@1280.9,4460.48 U11.14@1280.9,4525.13
NetR143_1: R143.1 TP40.1 U4.17 | length 93.6
  Top Layer w10: v1(1466.2,1712.09) 1470.93,1707.36 U4.17@1490.54,1707.36
  Bottom Layer w5: TP40.1@1443.78,1678.08 1444.01,1678.32 R143.1@1444.01,1719.9
  Bottom Layer w10: R143.1@1444.01,1719.9 1458.39,1719.9 v1(1466.2,1712.09)
NetR144_2: R144.2 R276.2 U19.19 | length 94.4
  Top Layer w15: R276.2@5106.49,867.94 R144.2@5106.49,902.15 5106.49,933.42 5119.48,946.41 U19.19@5119.48,956.94
NetR145_2: R145.2 U6.1 | length 34.4
  Bottom Layer w5: U6.1@2577.54,6199.46 2577.54,6206.46 2578.02,6206.94 R145.2@2604.69,6206.94
NetR146_2: R146.2 U62.1 | length 29.9
  Bottom Layer w6: U62.1@4019.49,6205.78 R146.2@4049.44,6205.78
NetR147_1: R147.1 R152.2 U13.4 | length 77.8
  Bottom Layer w4: U13.4@2616.83,6014.47 2616.83,5994.25 2633.72,5977.36 R152.2@2633.72,5969.02 2633.72,5944.71 R147.1@2633,5943.98
NetR148_1: R148.1 U13.5 | length 52.3
  Bottom Layer w10: R148.1@2585.9,5968.47 2585.9,5984.28 2601.08,5999.46 U13.5@2601.08,6014.47
NetR150_1: R150.1 U13.6 | length 41.9
  Bottom Layer w4: R150.1@2545.84,6008.77 2551.54,6014.47 U13.6@2585.33,6014.47
NetR153_1: R153.1 R156.2 U13.7 | length 61
  Bottom Layer w10: R156.2@2545.84,6056.5 R153.1@2545.84,6033.9 2548.06,6036.12 U13.7@2583.36,6036.12
NetR154_1: R154.1 U13.8 | length 56.3
  Bottom Layer w10: R154.1@2545.84,6080.37 2552.76,6080.37 2563.87,6069.26 2563.87,6057.42 2569.42,6051.87 U13.8@2583.36,6051.87
NetR155_2: R155.2 R327.1 U13.3 | length 81.5
  Bottom Layer w4: U13.3@2632.57,6014.47 2632.57,6002.09 2657.08,5977.58 2657.08,5968.86 2657.08,5945.41 R327.1@2658.73,5943.77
